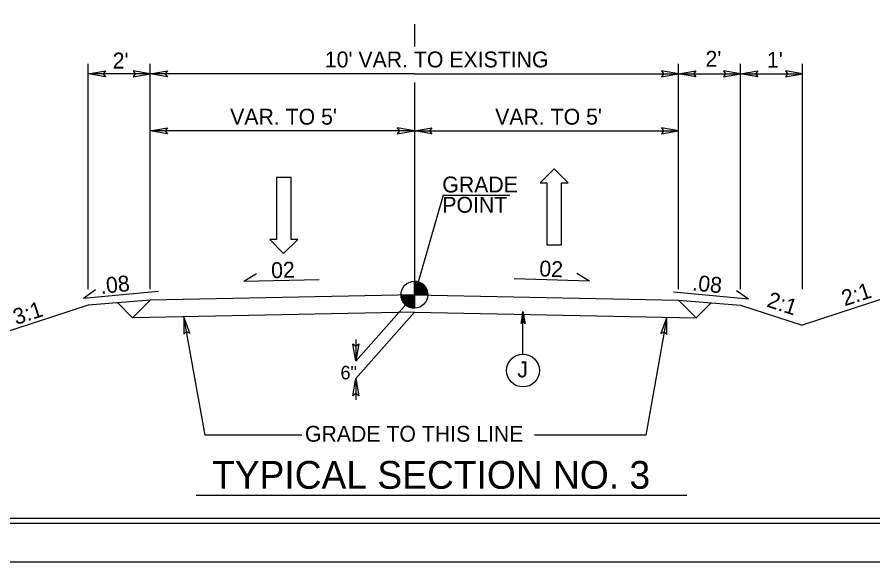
# Model space of a CAD drawing. Extents: x 2532463 to 2534146, y 189689 to 190784.
# Drawn here: x 2533259.8 to 2533701.3, y 189689.2 to 189970.5 of the extents above; entities that cross this region are included whole.
import ezdxf

# ---------------------------------------------------------------- set-up
doc = ezdxf.new("R2010")
doc.units = 0
for name, color, linetype in [('Old_Level_1', 7, 'Continuous'), ('Old_Level_12', 7, 'Continuous'), ('Old_Level_18', 7, 'Continuous'), ('Old_Level_2', 7, 'Continuous'), ('Old_Level_3', 7, 'Continuous'), ('Old_Level_4', 7, 'Continuous'), ('Old_Level_42', 7, 'Continuous'), ('Old_Level_50', 7, 'Continuous'), ('Old_Level_51', 7, 'Continuous')]:
    doc.layers.add(name, color=color, linetype=linetype)

msp = doc.modelspace()

# ---------------------------------------------------------------- linework, layer by layer
at = {"layer": 'Old_Level_1'}
for p, q in [((2533464.79, 189834.07), (2533464.79, 189827.12)), ((2533464.79, 189827.12), (2533464.79, 189834.07)), ((2533328.48, 189824.4), (2533296.48, 189821.84)), ((2533328.48, 189824.4), (2533319.35, 189815.27)), ((2533464.79, 189827.13), (2533328.48, 189824.4)), ((2533457.85, 189827.12), (2533464.79, 189827.12)), ((2533464.79, 189827.13), (2533601.11, 189824.4)), ((2533464.79, 189827.12), (2533464.79, 189820.18)), ((2533471.74, 189827.12), (2533464.79, 189827.12)), ((2533601.11, 189824.4), (2533610.24, 189815.27)), ((2533601.11, 189824.4), (2533633.11, 189821.84)), ((2533710.55, 189826.39), (2533664.91, 189811.38)), ((2533296.48, 189821.84), (2533193.06, 189787.82)), ((2533311.57, 189823.05), (2533319.35, 189815.27)), ((2533618.01, 189823.05), (2533610.24, 189815.27)), ((2533633.11, 189821.84), (2533664.91, 189811.38)), ((2533464.88, 189818.18), (2533319.35, 189815.27)), ((2533464.7, 189818.18), (2533610.24, 189815.27)), ((2533520.8, 189818.48), (2533519.7, 189812.24)), ((2533520.8, 189818.48), (2533519.86, 189812.36)), ((2533520.01, 189812.48), (2533520.8, 189818.48)), ((2533520.8, 189818.48), (2533520.17, 189812.59)), ((2533520.33, 189812.71), (2533520.8, 189818.48)), ((2533520.8, 189818.48), (2533520.49, 189812.82)), ((2533520.64, 189812.94), (2533520.8, 189818.48)), ((2533520.8, 189818.48), (2533521.9, 189812.24)), ((2533521.74, 189812.36), (2533520.8, 189818.48)), ((2533520.8, 189818.48), (2533521.58, 189812.48)), ((2533521.43, 189812.59), (2533520.8, 189818.48)), ((2533520.8, 189818.48), (2533521.27, 189812.71)), ((2533521.12, 189812.82), (2533520.8, 189818.48)), ((2533520.8, 189818.48), (2533520.96, 189812.94)), ((2533520.8, 189813.06), (2533520.8, 189818.48)), ((2533520.8, 189813.06), (2533519.7, 189812.24)), ((2533521.9, 189812.24), (2533520.8, 189813.06)), ((2533352.15, 189723.58), (2533605.33, 189723.58))]:
    msp.add_line(p, q, dxfattribs=at)
for points in [[(2533464.89, 189827.12), (2533464.89, 189834.07), (2533464.89, 189834.07)], [(2533465.03, 189827.12), (2533465.03, 189834.06)], [(2533465.16, 189827.12), (2533465.17, 189834.05)], [(2533465.31, 189827.12), (2533465.31, 189834.05)], [(2533465.44, 189827.12), (2533465.45, 189834.04)], [(2533465.59, 189827.12), (2533465.59, 189834.02)], [(2533465.72, 189827.12), (2533465.72, 189834.01)], [(2533465.86, 189827.12), (2533465.86, 189833.98)], [(2533466, 189827.12), (2533466, 189833.96)], [(2533466.14, 189827.12), (2533466.14, 189833.94)], [(2533466.28, 189827.12), (2533466.28, 189833.91)], [(2533466.42, 189827.12), (2533466.42, 189833.87)], [(2533466.56, 189827.12), (2533466.56, 189833.84)], [(2533466.69, 189827.12), (2533466.7, 189833.8)], [(2533466.84, 189827.12), (2533466.84, 189833.76)], [(2533466.97, 189827.12), (2533466.97, 189833.72)], [(2533467.11, 189827.12), (2533467.11, 189833.67)], [(2533467.25, 189827.12), (2533467.25, 189833.62)], [(2533467.39, 189827.12), (2533467.39, 189833.56)], [(2533467.53, 189827.12), (2533467.53, 189833.51)], [(2533467.67, 189827.12), (2533467.67, 189833.44)], [(2533467.81, 189827.12), (2533467.81, 189833.38)], [(2533467.94, 189827.12), (2533467.94, 189833.31)], [(2533468.09, 189827.12), (2533468.09, 189833.24)], [(2533468.22, 189827.12), (2533468.22, 189833.16)], [(2533468.36, 189827.12), (2533468.36, 189833.08)], [(2533468.5, 189827.12), (2533468.5, 189833)], [(2533468.64, 189827.12), (2533468.64, 189832.9)], [(2533468.78, 189827.12), (2533468.78, 189832.81)], [(2533468.92, 189827.12), (2533468.92, 189832.71)], [(2533469.06, 189827.12), (2533469.06, 189832.61)], [(2533469.19, 189827.12), (2533469.19, 189832.49)], [(2533469.33, 189827.12), (2533469.34, 189832.37)], [(2533469.47, 189827.12), (2533469.47, 189832.25)], [(2533469.61, 189827.12), (2533469.61, 189832.12)], [(2533469.75, 189827.12), (2533469.75, 189831.98)], [(2533469.89, 189827.12), (2533469.89, 189831.84)], [(2533470.03, 189827.12), (2533470.03, 189831.68)], [(2533470.17, 189827.12), (2533470.17, 189831.52)], [(2533470.3, 189827.12), (2533470.3, 189831.34)], [(2533470.44, 189827.12), (2533470.44, 189831.16)], [(2533470.58, 189827.12), (2533470.58, 189830.95)], [(2533470.72, 189827.12), (2533470.72, 189830.73)], [(2533470.86, 189827.12), (2533470.86, 189830.5)], [(2533471, 189827.12), (2533471, 189830.24)], [(2533471.14, 189827.12), (2533471.14, 189829.94)], [(2533471.27, 189827.12), (2533471.27, 189829.6)], [(2533471.42, 189827.12), (2533471.42, 189829.2)], [(2533471.55, 189827.12), (2533471.55, 189828.7)], [(2533457.92, 189826.14), (2533457.92, 189827.12)], [(2533458.06, 189825.44), (2533458.06, 189827.13)], [(2533458.2, 189824.96), (2533458.2, 189827.13)], [(2533458.34, 189824.57), (2533458.34, 189827.12)], [(2533458.47, 189824.25), (2533458.48, 189827.13)], [(2533458.61, 189823.95), (2533458.61, 189827.13)], [(2533458.75, 189823.7), (2533458.75, 189827.12)], [(2533458.89, 189823.47), (2533458.89, 189827.13)], [(2533459.03, 189823.25), (2533459.03, 189827.13)], [(2533459.17, 189823.05), (2533459.17, 189827.12)], [(2533459.31, 189822.87), (2533459.31, 189827.13)], [(2533459.44, 189822.7), (2533459.45, 189827.13)], [(2533459.59, 189822.53), (2533459.59, 189827.12)], [(2533459.72, 189822.38), (2533459.72, 189827.13)], [(2533459.86, 189822.24), (2533459.86, 189827.13)], [(2533460, 189822.1), (2533460, 189827.12)], [(2533460.14, 189821.97), (2533460.14, 189827.13)], [(2533460.28, 189821.85), (2533460.28, 189827.12)], [(2533460.42, 189821.73), (2533460.42, 189827.12)], [(2533460.56, 189821.63), (2533460.56, 189827.12)], [(2533460.69, 189821.52), (2533460.69, 189827.12)], [(2533460.84, 189821.42), (2533460.84, 189827.12)], [(2533460.97, 189821.33), (2533460.97, 189827.12)], [(2533461.11, 189821.24), (2533461.11, 189827.12)], [(2533461.25, 189821.15), (2533461.25, 189827.12)], [(2533461.39, 189821.07), (2533461.39, 189827.12)], [(2533461.53, 189821), (2533461.53, 189827.12)], [(2533461.67, 189820.92), (2533461.67, 189827.12)], [(2533461.81, 189820.86), (2533461.81, 189827.12)], [(2533461.94, 189820.79), (2533461.94, 189827.12)], [(2533462.08, 189820.73), (2533462.09, 189827.12)], [(2533462.22, 189820.67), (2533462.22, 189827.12)], [(2533462.36, 189820.62), (2533462.36, 189827.12)], [(2533462.5, 189820.57), (2533462.5, 189827.12)], [(2533462.64, 189820.52), (2533462.64, 189827.12)], [(2533462.78, 189820.48), (2533462.78, 189827.12)], [(2533462.92, 189820.44), (2533462.92, 189827.12)], [(2533463.05, 189820.4), (2533463.06, 189827.12)], [(2533463.2, 189820.37), (2533463.2, 189827.12)], [(2533463.33, 189820.33), (2533463.34, 189827.12)], [(2533463.47, 189820.31), (2533463.47, 189827.12)], [(2533463.61, 189820.28), (2533463.62, 189827.12)], [(2533463.75, 189820.26), (2533463.75, 189827.12)], [(2533463.89, 189820.24), (2533463.89, 189827.12)], [(2533464.03, 189820.22), (2533464.03, 189827.12)], [(2533464.17, 189820.21), (2533464.17, 189827.12)], [(2533464.3, 189820.2), (2533464.31, 189827.12)], [(2533464.45, 189820.19), (2533464.45, 189827.12)], [(2533464.58, 189820.19), (2533464.59, 189827.12)], [(2533464.72, 189820.18), (2533464.72, 189820.18), (2533464.72, 189827.12)], [(2533471.7, 189827.12), (2533471.7, 189827.88)]]:
    msp.add_lwpolyline(points, dxfattribs=at)
msp.add_circle((2533464.79, 189827.13), 6.94, dxfattribs=at)
for start, end in [(359.9906, 89.9906), (179.9906, 269.9906)]:
    msp.add_arc((2533464.79, 189827.13), 6.94, start, end, dxfattribs=at)
at = {"layer": 'Old_Level_18'}
msp.add_lwpolyline([(2534129.31, 190761.68), (2532629.31, 190761.68), (2532629.31, 189711.68), (2534129.31, 189711.68)], close=True, dxfattribs=at)
at = {"layer": 'Old_Level_2'}
for p, q in [((2533464.79, 189966.87), (2533464.79, 189955.41)), ((2533296.48, 189830.09), (2533296.48, 189946.37)), ((2533328.48, 189830.09), (2533328.48, 189946.37)), ((2533601.11, 189830.09), (2533601.11, 189946.37)), ((2533633.11, 189830.09), (2533633.11, 189946.37)), ((2533665.11, 189830.09), (2533665.11, 189946.37)), ((2533328.48, 189941.22), (2533296.48, 189941.22)), ((2533464.79, 189941.22), (2533328.48, 189941.22)), ((2533464.79, 189941.22), (2533601.11, 189941.22)), ((2533601.11, 189941.22), (2533633.11, 189941.22)), ((2533633.11, 189941.22), (2533665.11, 189941.22)), ((2533464.79, 189936.7), (2533464.79, 189823.09)), ((2533464.79, 189911.72), (2533328.48, 189911.72)), ((2533464.79, 189911.72), (2533601.11, 189911.72)), ((2533479.65, 189878.54), (2533464.79, 189827.12)), ((2533479.65, 189878.54), (2533513.95, 189878.54)), ((2533376.69, 189834.12), (2533383.21, 189838.08)), ((2533555.13, 189834.17), (2533548.65, 189838.19)), ((2533376.69, 189834.12), (2533415.55, 189835)), ((2533555.13, 189834.17), (2533516.29, 189835.4)), ((2533293.97, 189825.41), (2533300.2, 189829.82)), ((2533293.97, 189825.41), (2533332.67, 189829.02)), ((2533637.19, 189824.79), (2533630.97, 189829.2)), ((2533464.79, 189827.13), (2533434.47, 189792.83)), ((2533637.19, 189824.79), (2533598.5, 189828.4)), ((2533356.73, 189754.58), (2533345.81, 189815.8)), ((2533464.88, 189818.18), (2533434.56, 189783.88)), ((2533520.8, 189796.5), (2533520.8, 189818.48)), ((2533595.09, 189815.57), (2533584.21, 189754.58)), ((2533434.56, 189803.99), (2533434.56, 189792.93)), ((2533434.56, 189783.88), (2533434.56, 189772.81)), ((2533406.66, 189754.58), (2533356.73, 189754.58)), ((2533584.21, 189754.58), (2533526.79, 189754.58))]:
    msp.add_line(p, q, dxfattribs=at)
msp.add_circle((2533520.8, 189788), 8.5, dxfattribs=at)
at = {"layer": 'Old_Level_3'}
for p, q in [((2533296.48, 189941.22), (2533305.38, 189942.79)), ((2533305.38, 189939.65), (2533296.48, 189941.22)), ((2533305.38, 189942.79), (2533304.22, 189941.22)), ((2533304.22, 189941.22), (2533305.38, 189939.65)), ((2533328.48, 189941.22), (2533319.57, 189942.79)), ((2533319.57, 189942.79), (2533320.73, 189941.22)), ((2533319.57, 189939.65), (2533328.48, 189941.22)), ((2533320.73, 189941.22), (2533319.57, 189939.65)), ((2533328.48, 189941.22), (2533337.38, 189942.79)), ((2533337.38, 189939.65), (2533328.48, 189941.22)), ((2533337.38, 189942.79), (2533336.22, 189941.22)), ((2533336.22, 189941.22), (2533337.38, 189939.65)), ((2533601.11, 189941.22), (2533592.2, 189942.79)), ((2533592.2, 189942.79), (2533593.36, 189941.22)), ((2533592.2, 189939.65), (2533601.11, 189941.22)), ((2533593.36, 189941.22), (2533592.2, 189939.65)), ((2533601.11, 189941.22), (2533610.01, 189942.79)), ((2533610.01, 189939.65), (2533601.11, 189941.22)), ((2533610.01, 189942.79), (2533608.85, 189941.22)), ((2533608.85, 189941.22), (2533610.01, 189939.65)), ((2533633.11, 189941.22), (2533624.2, 189942.79)), ((2533624.2, 189942.79), (2533625.36, 189941.22)), ((2533624.2, 189939.65), (2533633.11, 189941.22)), ((2533625.36, 189941.22), (2533624.2, 189939.65)), ((2533633.11, 189941.22), (2533642.01, 189942.79)), ((2533642.01, 189939.65), (2533633.11, 189941.22)), ((2533642.01, 189942.79), (2533640.85, 189941.22)), ((2533640.85, 189941.22), (2533642.01, 189939.65)), ((2533665.11, 189941.22), (2533656.2, 189942.79)), ((2533656.2, 189942.79), (2533657.36, 189941.22)), ((2533656.2, 189939.65), (2533665.11, 189941.22)), ((2533657.36, 189941.22), (2533656.2, 189939.65)), ((2533328.48, 189911.72), (2533337.38, 189913.29)), ((2533337.38, 189913.29), (2533336.22, 189911.72)), ((2533464.79, 189911.72), (2533455.89, 189913.3)), ((2533455.89, 189913.3), (2533457.05, 189911.72)), ((2533464.79, 189911.72), (2533473.7, 189913.3)), ((2533473.7, 189913.3), (2533472.54, 189911.72)), ((2533601.11, 189911.72), (2533592.2, 189913.29)), ((2533592.2, 189913.29), (2533593.36, 189911.72)), ((2533337.38, 189910.15), (2533328.48, 189911.72)), ((2533336.22, 189911.72), (2533337.38, 189910.15)), ((2533455.89, 189910.15), (2533464.79, 189911.72)), ((2533457.05, 189911.72), (2533455.89, 189910.15)), ((2533473.7, 189910.15), (2533464.79, 189911.72)), ((2533472.54, 189911.72), (2533473.7, 189910.15)), ((2533592.2, 189910.15), (2533601.11, 189911.72)), ((2533593.36, 189911.72), (2533592.2, 189910.15)), ((2533348.92, 189807.3), (2533345.81, 189815.8)), ((2533345.81, 189815.8), (2533345.83, 189806.75)), ((2533595.09, 189815.57), (2533591.98, 189807.08)), ((2533595.07, 189806.53), (2533595.09, 189815.57)), ((2533345.83, 189806.75), (2533347.17, 189808.17)), ((2533347.17, 189808.17), (2533348.92, 189807.3)), ((2533591.98, 189807.08), (2533593.73, 189807.95)), ((2533593.73, 189807.95), (2533595.07, 189806.53)), ((2533434.56, 189792.93), (2533432.99, 189801.83)), ((2533432.99, 189801.83), (2533434.56, 189800.67)), ((2533436.13, 189801.83), (2533434.56, 189792.93)), ((2533434.56, 189800.67), (2533436.13, 189801.83)), ((2533432.99, 189774.97), (2533434.56, 189783.88)), ((2533434.56, 189783.88), (2533436.13, 189774.97)), ((2533434.56, 189776.13), (2533432.99, 189774.97)), ((2533436.13, 189774.97), (2533434.56, 189776.13))]:
    msp.add_line(p, q, dxfattribs=at)
at = {"layer": 'Old_Level_4'}
for p, q in [((2533536.97, 189892.24), (2533529.62, 189885.01)), ((2533544.08, 189885.01), (2533536.97, 189892.24)), ((2533393.56, 189887.74), (2533393.57, 189855.61)), ((2533401.13, 189887.74), (2533393.56, 189887.74)), ((2533401.15, 189855.61), (2533401.13, 189887.74)), ((2533529.62, 189885.01), (2533533.07, 189885.01)), ((2533533.07, 189885.01), (2533533.08, 189852.88)), ((2533540.65, 189852.88), (2533540.64, 189885.01)), ((2533540.64, 189885.01), (2533544.08, 189885.01)), ((2533393.57, 189855.61), (2533390.13, 189855.61)), ((2533390.13, 189855.61), (2533397.25, 189848.38)), ((2533397.25, 189848.38), (2533404.59, 189855.61)), ((2533404.59, 189855.61), (2533401.15, 189855.61)), ((2533533.08, 189852.88), (2533540.65, 189852.88))]:
    msp.add_line(p, q, dxfattribs=at)
at = {"layer": 'Old_Level_50'}
msp.add_lwpolyline([(2532475.81, 189709.18), (2534141.81, 189709.18), (2534141.81, 190764.18), (2532475.81, 190764.18)], close=True, dxfattribs=at)
at = {"layer": 'Old_Level_51'}
msp.add_lwpolyline([(2532462.81, 189689.18), (2534146.31, 189689.18), (2534146.31, 190784.18), (2532462.81, 190784.18)], close=True, dxfattribs=at)

# ---------------------------------------------------------------- texts
at = {"layer": 'Old_Level_12'}
for s, height, rotation, p in [("10' VAR. TO EXISTING ", 8.2009, 0.0001, (2533418.53, 189944.54)), ("VAR. TO 5'", 8.201, 359.9999, (2533369.69, 189914.98)), ("VAR. TO 5'", 8.201, 359.9999, (2533506.44, 189914.98)), ('J', 8.2, 359.9999, (2533517.9, 189784.47)), ('GRADE TO THIS LINE', 8.2009, 0.0001, (2533408.28, 189751.23))]:
    msp.add_text(s, height=height, rotation=rotation, dxfattribs=at).set_placement(p)
at = {"layer": 'Old_Level_2'}
for s, height, rotation, p in [("2'", 8.201, 359.9999, (2533309.06, 189943.95)), ("2'", 8.201, 0.0001, (2533614.97, 189944.89)), ("1'", 8.201, 0.0001, (2533646.66, 189944.36)), ('GRADE ', 8.201, 0.0001, (2533479.17, 189879.97)), ('POINT', 8.201, 0.0001, (2533479.17, 189869.49)), ('.08', 8.201, 5.8332, (2533303.03, 189827.56)), ('.08', 8.201, 354.1668, (2533607.88, 189829.41)), ('6"', 6.971, 0.0462, (2533426.63, 189783.44))]:
    msp.add_text(s, height=height, rotation=rotation, dxfattribs=at).set_placement(p)
at = {"layer": 'Old_Level_3'}
for s, height, rotation, p in [('02', 8.201, 1.6936, (2533390.95, 189835.68)), ('02', 8.201, 357.6199, (2533529.1, 189836.66)), ('TYPICAL SECTION NO. 3', 14.3518, 0.0001, (2533360.33, 189726.94))]:
    msp.add_text(s, height=height, rotation=rotation, dxfattribs=at).set_placement(p)
at = {"layer": 'Old_Level_42'}
for s, height, rotation, p in [('2:1', 8.201, 18.2581, (2533686.79, 189821.12)), ('2:1', 8.201, 341.7419, (2533646.13, 189821.14)), ('VAR. 2:1 TO 3:1', 8.2009, 18.2581, (2533197.34, 189791.03))]:
    msp.add_text(s, height=height, rotation=rotation, dxfattribs=at).set_placement(p)

doc.saveas('drawing.dxf')
